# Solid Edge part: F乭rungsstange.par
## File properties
Username: bmolnar
Dokumentum tartalom típus: 0
Author: bmolnar
Last saved by: bmolnar
Revision: 87
Sűrűség: 0,000 kg/m^3
Pontosság: 0,990
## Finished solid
Body 1: solid body, 8 faces, 7 edges, 1 vertex.
  Faces by surface: cone 4, cylinder 2, plane 2
  Edges by curve: circle 7
Bounding box of the edges (mm): 10.000 x 10.000 x 107.000, from (-5, -5, -91) to (5, 5, 16).
Cylindrical faces by radius (mm): R2.4585 x1, R5 x1
Conical faces (half-angle, radius in mm at the cone's reference point): 45 deg R2.6585 x1, 45 deg R4.95 x1, 45 deg R5 x1, 59 deg R1.2292 x1
Planar faces by outward normal: +z 1, -z 1
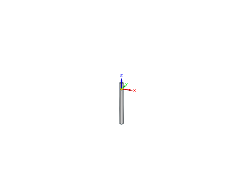
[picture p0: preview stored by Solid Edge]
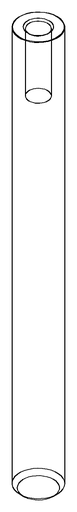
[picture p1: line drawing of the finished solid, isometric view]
